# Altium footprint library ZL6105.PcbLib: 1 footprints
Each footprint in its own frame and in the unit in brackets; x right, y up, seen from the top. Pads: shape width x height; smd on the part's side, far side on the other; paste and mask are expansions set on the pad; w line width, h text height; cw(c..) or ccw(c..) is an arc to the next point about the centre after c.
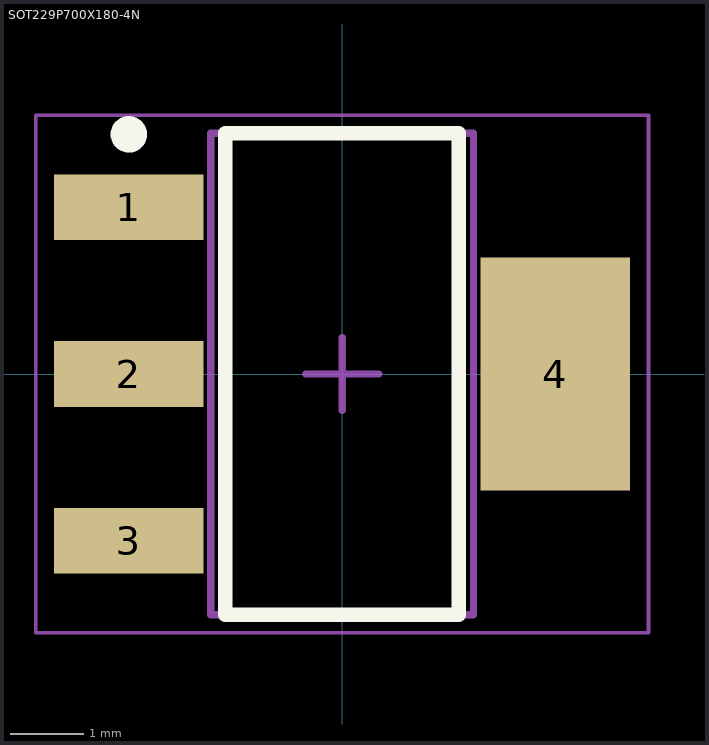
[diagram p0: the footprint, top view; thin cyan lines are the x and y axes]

## SOT229P700X180-4N [mm] "SOT223, 4-Leads, Body 6.50x7.00mm (avg), Pitch 2.29mm, IPC Medium Density"
height 1.8
pads (4):
  rect 2.05x0.9 smd: 1(-2.925,2.286) 2(-2.925,0) 3(-2.925,-2.286)
  rect 2.05x3.2 smd: 4(2.925,0)
Top Overlay:
  circle w0.25: c-2.925,3.286 r0.125
  lines w0.2: -1.6,-3.3 -1.6,3.3 1.6,3.3 1.6,-3.3 -1.6,-3.3
Mechanical 13:
  lines w0.1: -1.8,-3.3 -1.8,3.3 1.8,3.3 1.8,-3.3 -1.8,-3.3
Mechanical 15:
  lines w0.05: -4.2,-3.55 -4.2,3.55 4.2,3.55 4.2,-3.55 -4.2,-3.55
  lines w0.1: -0.5,0 0.5,0 ; 0,-0.5 0,0.5
3D body: height 1.8, standoff 0, extent -3.5,-3.3 3.5,3.3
